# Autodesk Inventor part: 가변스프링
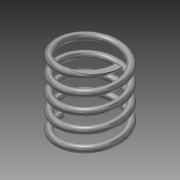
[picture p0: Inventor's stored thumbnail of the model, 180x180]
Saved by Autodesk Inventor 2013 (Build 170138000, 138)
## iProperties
Created: 2015-03
Part Number: 가변스프링
Material: 강철, 탄소
Document SubType Name: Modeling
Designer: Administrator
Density: 7.87 g/cm^3
Mass: 47.9501 g
Surface Area: 62.0098 cm^2
Volume: 6.09277 cm^3
Author: Administrator
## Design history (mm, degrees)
sketch "스케치2"
  geometry: L1 (0, 0)-(17.5, 0); L2 (17.5, 0)-(17.5, 43.5); L3 (17.5, 43.5)-(0, 43.5); L4 (0, 43.5)-(0, 0); C1 r 2 at (17.5, 0); 1 further point
  constraints: 8 end point, 2 parallel, 1 centre point, 1 coincident, 1 horizontal, 1 perpendicular
  dimensions: "d0" = 35 diameter of L2 L4; "d2" = 43.5 distance of L3.end L1.start (derived); "d3" = 4 diameter of C1
feature "코일1" sketch "스케치2" pitch "d4" = 10; turns "d6" = 4.5; dims "d5" = 43.5 (= d2), "d7" = 0, angle "d8" = 90 deg, angle "d9" = 90 deg, "d10" = 0, "d11" = 0
sketch "스케치5"
  geometry: L1 (0, -35)-(43.5, -35); L2 (43.5, -35)-(43.5, 35); L3 (43.5, 35)-(0, 35); L4 (0, 35)-(0, -35); 2 further points
  constraints: 8 end point, 2 parallel, 1 coincident, 1 horizontal, 1 midpoint, 1 perpendicular
  dimensions: "d12" = 70 distance of L1.end L2.end; "d14" = 43.5 distance of L2.end L3.end (derived)
extrude "돌출1" sketch "스케치5" stored distance "d15" = 0; taper "d16" = 0 deg
node "솔리드1"
